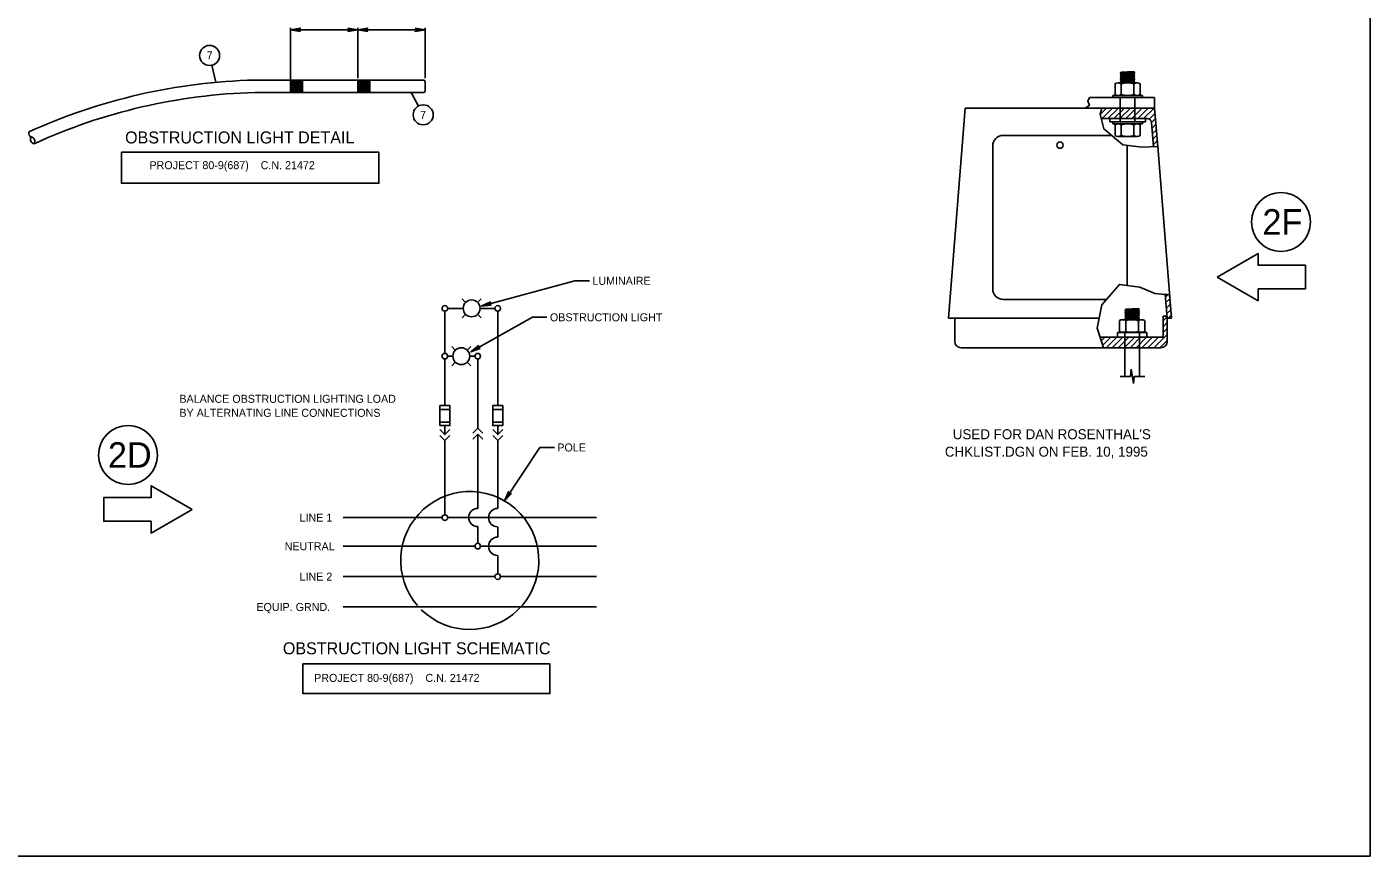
# Model space of a CAD drawing. Extents: x 99968 to 128667, y 90163 to 102182.
# Drawn here: x 106253 to 108267, y 99882 to 101126 of the extents above; entities that cross this region are included whole.
import ezdxf

# ---------------------------------------------------------------- set-up
doc = ezdxf.new("R2010")
doc.units = 0
for name, color, linetype in [('Border Prelim Stamp', 7, 'Continuous'), ('Default', 7, 'Continuous'), ('RD Standard Plans Active', 7, 'Continuous')]:
    doc.layers.add(name, color=color, linetype=linetype)

msp = doc.modelspace()

# ---------------------------------------------------------------- linework, layer by layer
at = {"layer": 'Border Prelim Stamp'}
for points in [[(108037.8, 100750.6), (108099.2, 100715.1), (108099.2, 100732.9), (108170.2, 100732.9), (108170.2, 100768.3), (108099.2, 100768.3), (108099.2, 100786.1)], [(106501, 100402), (106439.6, 100437.5), (106439.6, 100419.8), (106368.6, 100419.8), (106368.6, 100384.3), (106439.6, 100384.3), (106439.6, 100366.6)]]:
    msp.add_lwpolyline(points, close=True, dxfattribs=at)
for centre in [(108133.6, 100833.4), (106405.2, 100483.7)]:
    msp.add_circle(centre, 44.2, dxfattribs=at)
at = {"layer": 'Default'}
msp.add_lwpolyline([(105067.5, 102081.5), (108267.2, 102081.5), (108267.2, 99881.9), (105067.5, 99881.9)], close=True, dxfattribs=at)
at = {"layer": 'RD Standard Plans Active'}
for p, q in [((106648.6, 101049.1), (106648.6, 101124.6)), ((106648.6, 101121.6), (106749.5, 101121.6)), ((106749.5, 101049.1), (106749.5, 101124.6)), ((106749.5, 101121.6), (106850.3, 101121.6)), ((106850.3, 101049.1), (106850.3, 101124.6)), ((106536.9, 101042.8), (106530.8, 101068.5)), ((106648.6, 101046.1), (106648.6, 101052.3)), ((107894.1, 101057.9), (107892.6, 101056.2)), ((107892.6, 101056.2), (107914.6, 101057.4)), ((107892.6, 101056.2), (107894.1, 101054.7)), ((107894.1, 101054.7), (107892.6, 101053)), ((107892.6, 101053), (107914.6, 101054.2)), ((107892.6, 101053), (107894.1, 101051.5)), ((107894.1, 101051.5), (107892.6, 101049.9)), ((107892.6, 101049.9), (107914.6, 101051.1)), ((107894.1, 101057.9), (107913.1, 101058.9)), ((107894.1, 101054.7), (107913.1, 101055.7)), ((107894.1, 101051.5), (107913.1, 101052.5)), ((107914.6, 101057.4), (107913.1, 101058.9)), ((107913.1, 101055.7), (107914.6, 101057.4)), ((107914.6, 101054.2), (107913.1, 101055.7)), ((107913.1, 101052.5), (107914.6, 101054.2)), ((107914.6, 101051.1), (107913.1, 101052.5)), ((107913.1, 101049.4), (107914.6, 101051.1)), ((106595.1, 101046.1), (106847.9, 101046.1)), ((106648.6, 101027.5), (106648.6, 101046.1)), ((106650.6, 101027.5), (106650.6, 101046.1)), ((106652.6, 101027.5), (106652.6, 101046.1)), ((106654.6, 101027.5), (106654.6, 101046.1)), ((106656.6, 101027.5), (106656.6, 101046.1)), ((106658.6, 101027.5), (106658.6, 101046.1)), ((106660.6, 101027.5), (106660.6, 101046.1)), ((106662.6, 101027.5), (106662.6, 101046.1)), ((106664.6, 101027.5), (106664.6, 101046.1)), ((106666.6, 101027.5), (106666.6, 101046.1)), ((106749.6, 101027.5), (106749.6, 101046.1)), ((106751.6, 101027.5), (106751.6, 101046.1)), ((106753.6, 101027.5), (106753.6, 101046.1)), ((106755.6, 101027.5), (106755.6, 101046.1)), ((106757.6, 101027.5), (106757.6, 101046.1)), ((106759.6, 101027.5), (106759.6, 101046.1)), ((106761.6, 101027.5), (106761.6, 101046.1)), ((106763.6, 101027.5), (106763.6, 101046.1)), ((106765.6, 101027.5), (106765.6, 101046.1)), ((106767.6, 101027.5), (106767.6, 101046.1)), ((106850.3, 101029.9), (106850.3, 101043.7)), ((107884.7, 101024.4), (107884.7, 101040.6)), ((107889.4, 101042), (107917.8, 101042)), ((107892.6, 101049.9), (107894.1, 101048.4)), ((107894.1, 101048.4), (107892.6, 101046.7)), ((107892.6, 101046.7), (107914.6, 101047.9)), ((107892.6, 101046.7), (107894.1, 101045.2)), ((107894.1, 101045.2), (107892.6, 101043.6)), ((107892.6, 101043.6), (107914.6, 101044.7)), ((107892.6, 101043.6), (107894.1, 101042.1)), ((107894.1, 101048.4), (107913.1, 101049.4)), ((107894.1, 101045.2), (107913.1, 101046.2)), ((107894.1, 101042.1), (107913.1, 101043.1)), ((107894.1, 101024.4), (107894.1, 101040.6)), ((107914.6, 101047.9), (107913.1, 101049.4)), ((107913.1, 101046.2), (107914.6, 101047.9)), ((107914.6, 101044.7), (107913.1, 101046.2)), ((107913.1, 101043.1), (107914.6, 101044.7)), ((107914.3, 101042), (107913.1, 101043.1)), ((107913.1, 101024.4), (107913.1, 101040.6)), ((107922.5, 101024.4), (107922.5, 101040.6)), ((106595.1, 101027.5), (106847.9, 101027.5)), ((106829.7, 101027.5), (106840.5, 101007.2)), ((107846.7, 101019.9), (107944.1, 101019.9)), ((107881.5, 101023), (107925.7, 101023)), ((107881.5, 101023), (107881.5, 101019.9)), ((107889.4, 101023), (107917.8, 101023)), ((107892.6, 101019.9), (107892.6, 100988.3)), ((107914.6, 101019.9), (107914.6, 100988.3)), ((107925.7, 101023), (107925.7, 101019.9)), ((107944.1, 101004.1), (107944.1, 101019.9)), ((107635.1, 100688.8), (107660.3, 101004.1)), ((107660.3, 101004.1), (107864.9, 101004.1)), ((107862.3, 100994.8), (107864.9, 101004.1)), ((107864, 100988.3), (107862.3, 100994.8)), ((107862.4, 100994.4), (107872, 101004.1)), ((107864.9, 101004.1), (107944.1, 101004.1)), ((107865.2, 100988.3), (107881, 101004.1)), ((107874.1, 100988.3), (107889.9, 101004.1)), ((107883, 100988.3), (107898.8, 101004.1)), ((107891.9, 100988.3), (107907.7, 101004.1)), ((107900.9, 100988.3), (107916.6, 101004.1)), ((107909.8, 100988.3), (107925.5, 101004.1)), ((107918.7, 100988.3), (107934.5, 101004.1)), ((107927.6, 100988.3), (107943.4, 101004.1)), ((107935.9, 100987.7), (107944.7, 100996.5)), ((107944.1, 101004.1), (107948.7, 100946.4)), ((107933.2, 100988.3), (107864, 100988.3)), ((107876.8, 100983.6), (107876.8, 100988.3)), ((107876.8, 100983.6), (107930.4, 100983.6)), ((107881.5, 100980.5), (107881.5, 100983.6)), ((107881.5, 100980.5), (107925.7, 100980.5)), ((107884.7, 100979.1), (107884.7, 100962.9)), ((107889.4, 100980.5), (107917.8, 100980.5)), ((107892.6, 100983.6), (107892.6, 100988.3)), ((107894.1, 100979.1), (107894.1, 100962.9)), ((107913.1, 100979.1), (107913.1, 100962.9)), ((107914.6, 100983.6), (107914.6, 100988.3)), ((107922.5, 100979.1), (107922.5, 100962.9)), ((107925.7, 100980.5), (107925.7, 100983.6)), ((107930.4, 100983.6), (107930.4, 100988.3)), ((107939.5, 100982.4), (107945.4, 100988.3)), ((107942.4, 100946.2), (107939.5, 100982.5)), ((107940.2, 100974.1), (107946, 100980)), ((107940.8, 100965.9), (107946.7, 100971.7)), ((107717.1, 100963.1), (107879.8, 100963.1)), ((107889.4, 100961.5), (107917.8, 100961.5)), ((107941.5, 100957.6), (107947.4, 100963.5)), ((107942.2, 100949.4), (107948, 100955.2)), ((107701.3, 100732.9), (107701.3, 100947.4)), ((107903.1, 100738.1), (107903.1, 100948.2)), ((107948.7, 100946.4), (107942.4, 100946.2)), ((107948.1, 100946.4), (107948.7, 100947)), ((107969.3, 100688.8), (107948.7, 100946.4)), ((107075, 100745), (106934.5, 100707)), ((107096.8, 100745), (107075, 100745)), ((106911.2, 100712.7), (106905.9, 100718)), ((106929.1, 100712.7), (106934.5, 100718)), ((107717.1, 100717.2), (107871.8, 100717.2)), ((107963, 100688.8), (107960.1, 100724.8)), ((107960.1, 100724.8), (107966.5, 100724.2)), ((107960.5, 100720.5), (107964.4, 100724.4)), ((107961.1, 100712.3), (107967, 100718.1)), ((107961.8, 100704), (107967.6, 100709.9)), ((107966.5, 100724.2), (107969.3, 100688.8)), ((106880.1, 100699.5), (106880.1, 100636.2)), ((106884.3, 100703.7), (106907.5, 100703.7)), ((106905.9, 100689.4), (106911.2, 100694.8)), ((107011.3, 100690.3), (106919, 100638.4)), ((106934.5, 100689.4), (106929.1, 100694.8)), ((106932.9, 100703.7), (106955.1, 100703.7)), ((106959.3, 100699.5), (106959.3, 100557.9)), ((107033.1, 100690.3), (107011.3, 100690.3)), ((107635.1, 100688.8), (107860.9, 100688.8)), ((107644.5, 100654.1), (107644.5, 100688.8)), ((107900.8, 100702.6), (107899.2, 100700.9)), ((107899.2, 100700.9), (107921.3, 100702.1)), ((107899.2, 100700.9), (107900.8, 100699.4)), ((107900.8, 100699.4), (107899.2, 100697.7)), ((107899.2, 100697.7), (107921.3, 100698.9)), ((107899.2, 100697.7), (107900.8, 100696.2)), ((107900.8, 100696.2), (107899.2, 100694.6)), ((107899.2, 100694.6), (107921.3, 100695.8)), ((107899.2, 100694.6), (107900.8, 100693.1)), ((107900.8, 100693.1), (107899.2, 100691.4)), ((107899.2, 100691.4), (107921.3, 100692.6)), ((107899.2, 100691.4), (107900.8, 100689.9)), ((107900.8, 100689.9), (107899.2, 100688.3)), ((107899.2, 100688.3), (107921.3, 100689.4)), ((107899.2, 100688.3), (107900.8, 100686.8)), ((107900.8, 100702.6), (107919.7, 100703.6)), ((107900.8, 100699.4), (107919.7, 100700.4)), ((107900.8, 100696.2), (107919.7, 100697.2)), ((107900.8, 100693.1), (107919.7, 100694.1)), ((107900.8, 100689.9), (107919.7, 100690.9)), ((107900.8, 100686.8), (107919.7, 100687.8)), ((107921.3, 100702.1), (107919.7, 100703.6)), ((107919.7, 100700.4), (107921.3, 100702.1)), ((107921.3, 100698.9), (107919.7, 100700.4)), ((107919.7, 100697.2), (107921.3, 100698.9)), ((107921.3, 100695.8), (107919.7, 100697.2)), ((107919.7, 100694.1), (107921.3, 100695.8)), ((107921.3, 100692.6), (107919.7, 100694.1)), ((107919.7, 100690.9), (107921.3, 100692.6)), ((107921.3, 100689.4), (107919.7, 100690.9)), ((107919.7, 100687.8), (107921.3, 100689.4)), ((107920.9, 100686.7), (107919.7, 100687.8)), ((107956.7, 100691.9), (107962.8, 100691.9)), ((107956.7, 100660.4), (107956.7, 100691.9)), ((107956.7, 100685.1), (107962.8, 100691.2)), ((107962.4, 100695.8), (107968.3, 100701.6)), ((107963, 100688.8), (107969.3, 100688.8)), ((107963, 100688.8), (107963, 100654.1)), ((107969.3, 100688.8), (107963, 100688.8)), ((107964.4, 100688.8), (107969, 100693.4)), ((107888.2, 100667.7), (107932.3, 100667.7)), ((107888.2, 100667.7), (107888.2, 100660.4)), ((107891.3, 100669.1), (107891.3, 100685.3)), ((107896.1, 100686.7), (107924.4, 100686.7)), ((107896.1, 100667.7), (107924.4, 100667.7)), ((107899.2, 100667.7), (107899.2, 100660.6)), ((107900.8, 100669.1), (107900.8, 100685.3)), ((107919.7, 100669.1), (107919.7, 100685.3)), ((107921.3, 100667.7), (107921.3, 100660.6)), ((107929.2, 100669.1), (107929.2, 100685.3)), ((107932.3, 100667.7), (107932.3, 100660.4)), ((107956.7, 100676.2), (107963, 100682.5)), ((107956.7, 100667.3), (107963, 100673.6)), ((107867.6, 100644.6), (107862.5, 100660.4)), ((107862.5, 100660.4), (107956.7, 100660.4)), ((107864.2, 100655.1), (107869.6, 100660.4)), ((107866.4, 100648.3), (107878.5, 100660.4)), ((107871.6, 100644.6), (107887.4, 100660.4)), ((107880.5, 100644.6), (107896.3, 100660.4)), ((107889.5, 100644.6), (107905.2, 100660.4)), ((107898.4, 100644.6), (107914.2, 100660.4)), ((107899.2, 100660.6), (107899.2, 100601.6)), ((107907.3, 100644.6), (107923.1, 100660.4)), ((107916.2, 100644.6), (107932, 100660.4)), ((107921.3, 100660.6), (107921.3, 100601.6)), ((107925.1, 100644.6), (107940.9, 100660.4)), ((107934.1, 100644.6), (107949.8, 100660.4)), ((107943, 100644.6), (107963, 100664.7)), ((107951.9, 100644.6), (107963, 100655.7)), ((106880.1, 100627.8), (106880.1, 100557.9)), ((106884.3, 100632), (106892, 100632)), ((106895.7, 100640.9), (106890.4, 100646.3)), ((106913.6, 100640.9), (106919, 100646.3)), ((106917.3, 100632), (106925.1, 100632)), ((106929.3, 100627.8), (106929.3, 100523.9)), ((107654, 100644.6), (107953.5, 100644.6)), ((107953.5, 100644.6), (107867.6, 100644.6)), ((106890.4, 100617.7), (106895.7, 100623)), ((106919, 100617.7), (106913.6, 100623)), ((107908, 100601.6), (107908.8, 100612.3)), ((107908.8, 100612.3), (107912.6, 100591)), ((107892.2, 100601.6), (107908, 100601.6)), ((107913.5, 100601.6), (107912.6, 100591)), ((107913.5, 100601.6), (107929.2, 100601.6)), ((106872.6, 100552.2), (106887.6, 100552.2)), ((106966.8, 100552.2), (106951.8, 100552.2)), ((106872.6, 100533.1), (106887.6, 100533.1)), ((106880.1, 100527.8), (106880.1, 100514.3)), ((106966.8, 100533.1), (106951.8, 100533.1)), ((106959.3, 100527.8), (106959.3, 100514.3)), ((106929.3, 100501.4), (106929.3, 100514.9)), ((106880.1, 100505.3), (106880.1, 100394)), ((106929.3, 100505.3), (106929.3, 100403.7)), ((106959.3, 100505.3), (106959.3, 100403.5)), ((107022.5, 100495), (106969.4, 100414.9)), ((107044.2, 100495), (107022.5, 100495)), ((106727.4, 100389.7), (106875.9, 100389.7)), ((106884.3, 100389.7), (107107.5, 100389.7)), ((106929.3, 100376.3), (106929.3, 100351.2)), ((106959.3, 100376), (106959.3, 100360.6)), ((106727.4, 100346.8), (106925.1, 100346.8)), ((106933.5, 100346.8), (107107.5, 100346.8)), ((106959.3, 100333.1), (106959.3, 100305.5)), ((106727.4, 100301.3), (106955.1, 100301.3)), ((106963.5, 100301.3), (107107.5, 100301.3)), ((106727.4, 100255.7), (107107.5, 100255.7))]:
    msp.add_line(p, q, dxfattribs=at)
for points in [[(106663.5, 101119.1), (106648.6, 101121.6), (106663.5, 101124.1), (106661.2, 101121.6)], [(106734.6, 101124.1), (106749.5, 101121.6), (106734.6, 101119.1), (106736.9, 101121.6)], [(106764.4, 101119.1), (106749.5, 101121.6), (106764.4, 101124.1), (106762, 101121.6)], [(106835.4, 101124.1), (106850.3, 101121.6), (106835.4, 101119.1), (106837.8, 101121.6)], [(106395.2, 100938), (106781.3, 100938), (106781.3, 100891.4), (106395.2, 100891.4)], [(106949.6, 100708.5), (106934.5, 100707), (106948.3, 100713.4), (106946.7, 100710.3)], [(106933.2, 100643.5), (106919, 100638.4), (106930.7, 100647.9), (106929.9, 100644.6)], [(106872.6, 100527.8), (106887.6, 100527.8), (106887.6, 100557.8), (106872.6, 100557.8)], [(106966.8, 100527.8), (106951.8, 100527.8), (106951.8, 100557.8), (106966.8, 100557.8)], [(106979.8, 100425.9), (106969.4, 100414.9), (106975.5, 100428.7), (106976.4, 100425.4)], [(106667.3, 100170.4), (107037.6, 100170.4), (107037.6, 100125.8), (106667.3, 100125.8)]]:
    msp.add_lwpolyline(points, close=True, dxfattribs=at)
for points in [[(107846.7, 101019.9), (107844.1, 101014.3), (107846.3, 101008.6), (107840.5, 101004.1)], [(107864.9, 101004.1), (107862.3, 100994.8), (107868, 100973), (107896.5, 100949.1), (107925.3, 100945.5), (107948.7, 100946.4)], [(107966.5, 100724.2), (107944.4, 100726.2), (107921.7, 100735.7), (107891.3, 100739.5), (107864.8, 100709.2), (107858.1, 100674.1), (107867.6, 100644.6)], [(106872.6, 100521.8), (106880.1, 100514.3), (106887.6, 100521.8)], [(106872.6, 100512.8), (106880.1, 100505.3), (106887.6, 100512.8)], [(106921.8, 100516.4), (106929.3, 100523.9), (106936.8, 100516.4)], [(106921.8, 100507.4), (106929.3, 100514.9), (106936.8, 100507.4)], [(106966.8, 100521.8), (106959.3, 100514.3), (106951.8, 100521.8)], [(106966.8, 100512.8), (106959.3, 100505.3), (106951.8, 100512.8)]]:
    msp.add_lwpolyline(points, dxfattribs=at)
for centre, radius in [((106527.4, 101083.1), 15), ((106847.6, 100994), 15), ((107802.2, 100948.6), 4.73), ((106880.1, 100703.7), 4.2), ((106920.2, 100703.7), 12.7), ((106959.3, 100703.7), 4.2), ((106880.1, 100632), 4.2), ((106904.7, 100632), 12.7), ((106929.3, 100632), 4.2), ((106880.1, 100389.8), 4.2), ((106929.3, 100347), 4.2), ((106959.3, 100301.3), 4.2)]:
    msp.add_circle(centre, radius, dxfattribs=at)
for centre, radius, start, end in [((106615.6, 100181.8), 864.6, 91.3612, 114.5409), ((106847.9, 101043.7), 2.4, 0, 90), ((107889.4, 101033.1), 8.82, 57.5852, 122.4148), ((107903.6, 101008.7), 33.2, 73.4618, 106.5382), ((107917.8, 101033.1), 8.82, 57.5852, 122.4148), ((106617.7, 100179.4), 848.4, 91.526, 114.6065), ((106847.9, 101029.9), 2.4, 271.2458, 0), ((107889.4, 101031.9), 8.82, 237.5852, 302.4148), ((107903.6, 101056.3), 33.2, 253.4618, 286.5382), ((107917.8, 101031.9), 8.82, 237.5852, 302.4148), ((107889.4, 100971.6), 8.82, 57.5852, 122.4148), ((107903.6, 100947.2), 33.2, 73.4618, 106.5382), ((107917.8, 100971.6), 8.82, 57.5852, 122.4148), ((107933.2, 100982), 6.31, 4.5797, 90), ((106263.1, 100966.7), 6.81, 166.7853, 239.591), ((106265.6, 100957.4), 6.81, 149.7575, 260.0494), ((106258.5, 100954.1), 6.81, 329.7575, 80.0494), ((107717.1, 100947.4), 15.8, 90, 180), ((107889.4, 100970.4), 8.82, 237.5852, 302.4148), ((107903.6, 100994.8), 33.2, 253.4618, 286.5382), ((107917.8, 100970.4), 8.82, 237.5852, 302.4148), ((107717.1, 100732.9), 15.8, 180, 270), ((107896.1, 100677.8), 8.82, 57.5852, 122.4148), ((107896.1, 100676.6), 8.82, 237.5852, 302.4148), ((107910.2, 100653.4), 33.2, 73.4618, 106.5382), ((107910.2, 100701), 33.2, 253.4618, 286.5382), ((107924.4, 100677.8), 8.82, 57.5852, 122.4148), ((107924.4, 100676.6), 8.82, 237.5852, 302.4148), ((107654, 100654.1), 9.46, 180, 270), ((107953.5, 100654.1), 9.46, 270, 360), ((106917.4, 100325.4), 103.5, 225.4269, 220.7362), ((106929.4, 100390), 13.7, 90, 270), ((106959.2, 100389.8), 13.7, 90, 270), ((106959.2, 100346.8), 13.7, 90, 270)]:
    msp.add_arc(centre, radius, start, end, dxfattribs=at)

# ---------------------------------------------------------------- texts
at = {"layer": 'Border Prelim Stamp'}
for s, p in [('2F', (108105.7, 100814.2)), ('2D', (106375, 100464.6))]:
    msp.add_text(s, height=38.31, dxfattribs=at).set_placement(p)
at = {"layer": 'RD Standard Plans Active'}
for s, height, p in [('7', 12, (106522.9, 101077.1)), ('7', 12, (106843, 100988)), ('OBSTRUCTION LIGHT DETAIL', 18, (106400.7, 100951.1)), ('PROJECT 80-9(687)    C.N. 21472', 12, (106437.2, 100912.5)), (' LUMINAIRE', 12, (107096.8, 100739)), (' OBSTRUCTION LIGHT', 12, (107033.1, 100684.3)), ('BALANCE OBSTRUCTION LIGHTING LOAD', 12, (106482.1, 100562)), ('BY ALTERNATING LINE CONNECTIONS', 12, (106482.1, 100541)), ("USED FOR DAN ROSENTHAL'S", 15, (107641.5, 100507.4)), (' POLE', 12, (107044.2, 100489)), ('CHKLIST.DGN ON FEB. 10, 1995', 15, (107629.6, 100481.2)), ('LINE 1 ', 12, (106662.3, 100383.7)), ('NEUTRAL ', 12, (106639.9, 100340.8)), ('LINE 2 ', 12, (106662.3, 100295.3)), ('EQUIP. GRND. ', 12, (106597.5, 100249.7)), ('OBSTRUCTION LIGHT SCHEMATIC', 18, (106637.2, 100184.7)), ('PROJECT 80-9(687)    C.N. 21472', 12, (106684.1, 100143.3))]:
    msp.add_text(s, height=height, dxfattribs=at).set_placement(p)

doc.saveas('drawing.dxf')
